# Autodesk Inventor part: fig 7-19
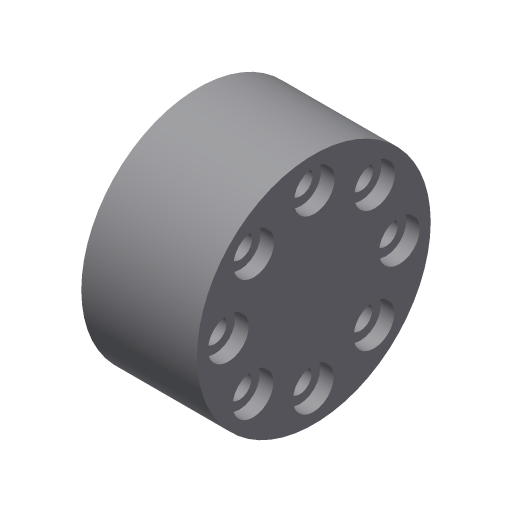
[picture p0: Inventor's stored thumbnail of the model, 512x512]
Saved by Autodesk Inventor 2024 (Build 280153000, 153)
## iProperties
Created: 2004-05
Part Number: fig 7-19
Document SubType Name: Modeling
Designer: CADCIM Technologies
Manufacturer: Standard
Standards Organization: Custom
Density: 1 g/cm^3
Material: Generic
Appearance: Default
Author: CADCIM Technologies
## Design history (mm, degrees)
sketch "Sketch1"
  geometry: C1 r 17.175 at (0, 0)
  constraints: 1 centre point
extrude "Extrusion1" new body sketch "Sketch1" distance "d0" = 17; taper "d1" = 0 deg
sketch "Sketch2"
  geometry: 1 further point
hole "Hole1" sketch "Sketch2" at (12.571, -0.074) diameter "d2" = 3.5; stored, may be unused: countersink angle "d6" = 90 deg, drill point angle "d8" = 118 deg; dims "d3" = 6, "d4" = 6, "d5" = 2, "d7" = 8
pattern_circular "Circular Pattern1" dims angle "d11" = 360 deg
body "Solid1"
